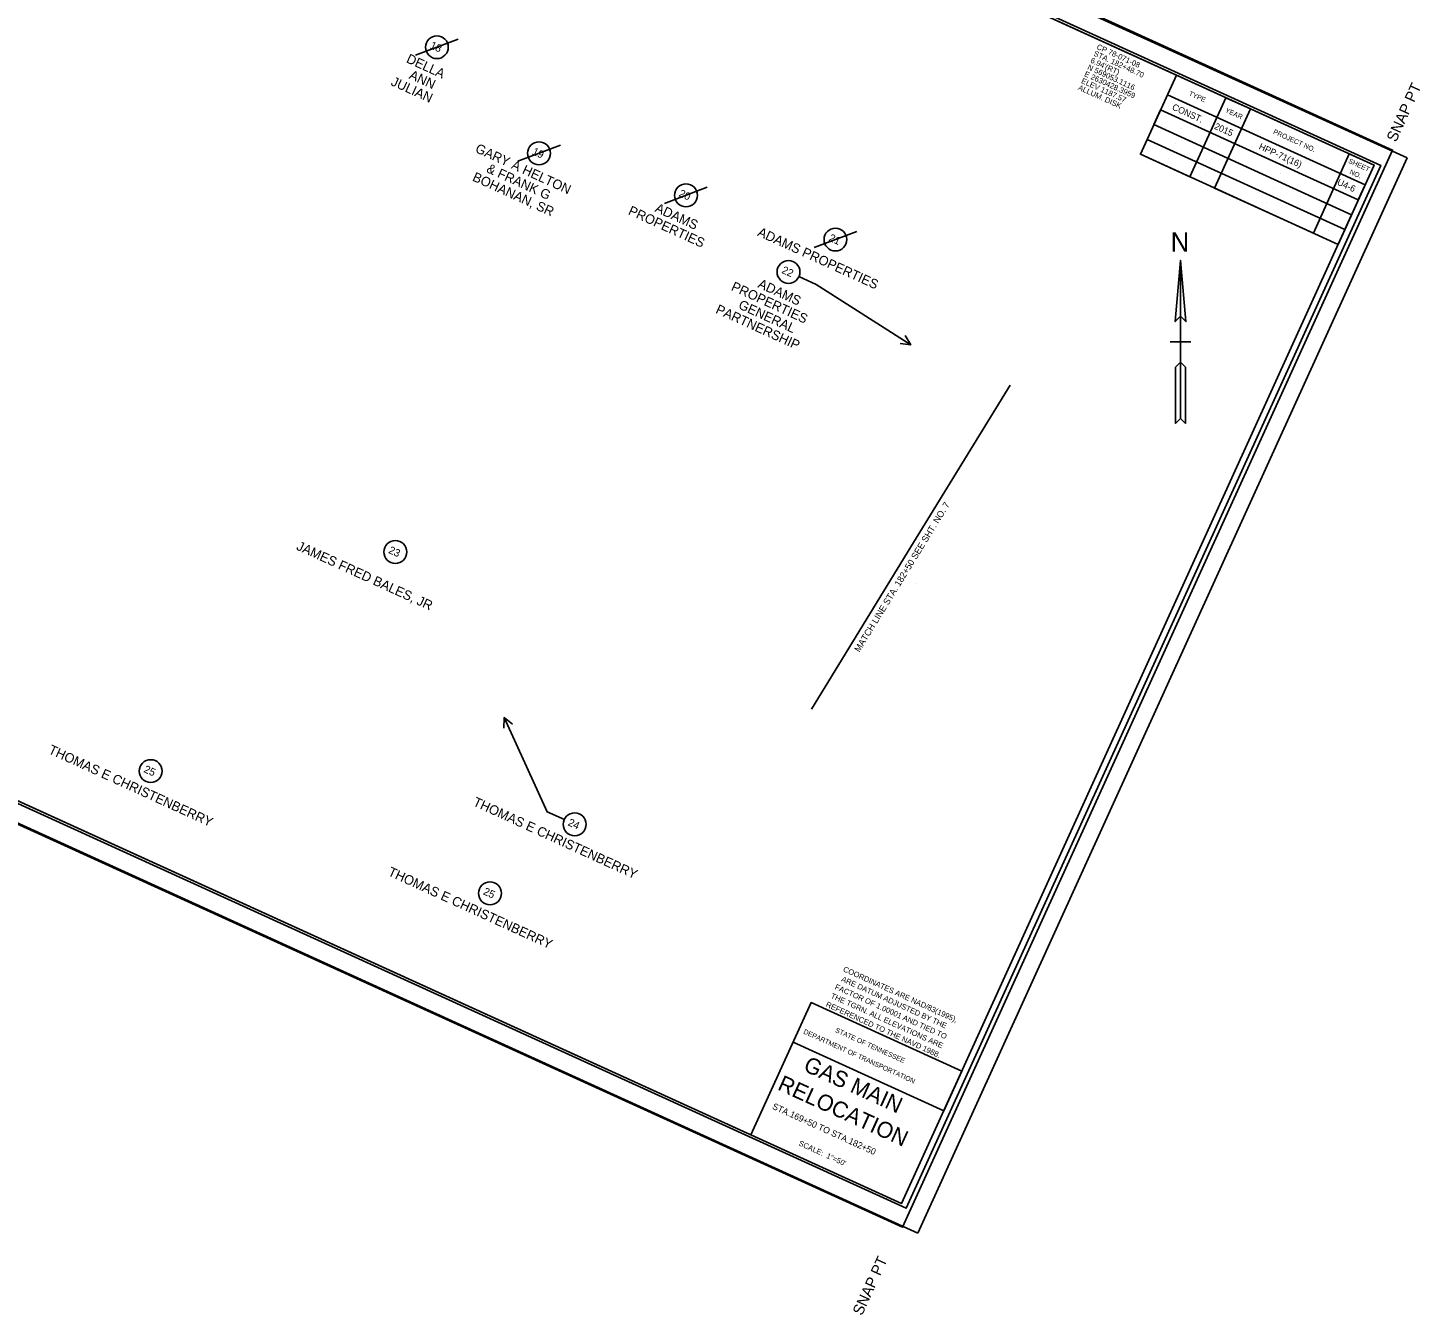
# Model space of a CAD drawing. Extents: x 2628810 to 2630911, y 568379 to 570218.
# Drawn here: x 2629628 to 2630911, y 568379 to 569564 of the extents above; entities that cross this region are included whole.
import ezdxf

# ---------------------------------------------------------------- set-up
doc = ezdxf.new("R2010")
doc.units = 0
for name, color, linetype in [('DESIGN - CENTERLINE - Proposed', 7, 'Continuous'), ('DESIGN - CENTERLINE - Proposed Text', 7, 'Continuous'), ('DESIGN - SCRATCH - User 1', 7, 'Continuous'), ('DESIGN - SHEET - Corner Text', 7, 'Continuous'), ('DESIGN - SHEET - Light Grid', 7, 'Continuous'), ('DESIGN - SHEET - Linework', 7, 'Continuous'), ('DESIGN - SHEET - Plot Shape', 7, 'Continuous'), ('SURVEY - PROPERTY - Owners', 7, 'Continuous'), ('SURVEY - PROPERTY - Tract Numbers', 7, 'Continuous')]:
    doc.layers.add(name, color=color, linetype=linetype)

msp = doc.modelspace()

# ---------------------------------------------------------------- linework, layer by layer
at = {"layer": 'DESIGN - CENTERLINE - Proposed Text'}
for p, q in [((2630689.9, 569274.6), (2630680.4, 569274.6)), ((2630699.3, 569274.6), (2630689.9, 569274.6))]:
    msp.add_line(p, q, dxfattribs=at)
for points in [[(2630689.9, 569349.6), (2630685, 569293.3), (2630689.9, 569298.2), (2630694.8, 569293.3), (2630689.9, 569349.6), (2630689.9, 569204.2), (2630694.4, 569199.6), (2630694.4, 569251.4), (2630689.9, 569255.9), (2630685.3, 569251.4), (2630685.3, 569199.6), (2630689.9, 569204.2)], [(2630349.9, 568936.6), (2630441.4, 569085.8), (2630532.9, 569234.9)]]:
    msp.add_lwpolyline(points, dxfattribs=at)
for points in [[(2630689.9, 569298.2), (2630694.8, 569293.3), (2630689.9, 569349.6)], [(2630685.3, 569199.6), (2630689.9, 569204.2), (2630689.9, 569255.9), (2630685.3, 569251.4)]]:
    msp.add_lwpolyline(points, close=True, dxfattribs=at)
at = {"layer": 'DESIGN - SCRATCH - User 1'}
for p, q in [((2630697.4, 569484.7), (2630697.4, 569484.7)), ((2630691.2, 569471.1), (2630691.2, 569471.1)), ((2630731.1, 569469.4), (2630731.1, 569469.4)), ((2630685, 569457.4), (2630685, 569457.4)), ((2630724.9, 569455.7), (2630724.9, 569455.7)), ((2630678.8, 569443.8), (2630678.8, 569443.8)), ((2630718.7, 569442.1), (2630718.7, 569442.1)), ((2630788, 569443.5), (2630788, 569443.5)), ((2630712.4, 569428.4), (2630712.4, 569428.4)), ((2630781.7, 569429.9), (2630781.7, 569429.9)), ((2630775.5, 569416.2), (2630775.5, 569416.2)), ((2630844.8, 569417.6), (2630844.8, 569417.6)), ((2630769.3, 569402.6), (2630769.3, 569402.6)), ((2630838.6, 569404), (2630838.6, 569404)), ((2630832.4, 569390.3), (2630832.4, 569390.3)), ((2630826.2, 569376.7), (2630826.2, 569376.7)), ((2630446.5, 569052.3), (2630446.5, 569052.3)), ((2630383, 568555.8), (2630383, 568555.8))]:
    msp.add_line(p, q, dxfattribs=at)
at = {"layer": 'DESIGN - SHEET - Light Grid'}
msp.add_lwpolyline([(2628921.9, 569166.8), (2630437.2, 568477), (2630874.3, 569437.1), (2629359, 570127)], close=True, dxfattribs=at)
at = {"layer": 'DESIGN - SHEET - Linework'}
for p, q in [((2629260.3, 570189.7), (2630898.6, 569443.9)), ((2630898.6, 569443.9), (2630448, 568454.2)), ((2628809.8, 569200), (2630448, 568454.2))]:
    msp.add_line(p, q, dxfattribs=at)
for points in [[(2629435.3, 570089.5), (2629000.3, 569133.8), (2630433, 568481.6), (2630868.1, 569437.3), (2629435.3, 570089.5)], [(2630686, 569520.1), (2630652.9, 569447.3), (2630834.9, 569364.4), (2630868.1, 569437.3), (2630845.3, 569447.6), (2630812.2, 569374.8), (2630721.2, 569416.2), (2630754.3, 569489), (2630731.6, 569499.4), (2630698.4, 569426.6), (2630652.9, 569447.3), (2630659.1, 569461), (2630841.1, 569378.1), (2630847.4, 569391.7), (2630665.3, 569474.6), (2630671.5, 569488.3), (2630853.6, 569405.4), (2630859.8, 569419.1), (2630677.8, 569501.9)], [(2630294.2, 568544.8), (2630349.6, 568666.4), (2630488.4, 568603.3), (2630471.8, 568566.9), (2630333, 568630)]]:
    msp.add_lwpolyline(points, dxfattribs=at)
at = {"layer": 'DESIGN - SHEET - Plot Shape'}
for points in [[(2629338, 570155.5), (2630885.2, 569451.1), (2630433.8, 568459.6), (2628886.6, 569164)], [(2629357.9, 570124.7), (2630868.1, 569437.3), (2630433, 568481.6), (2628922.9, 569169.1)]]:
    msp.add_lwpolyline(points, close=True, dxfattribs=at)
at = {"layer": 'SURVEY - PROPERTY - Tract Numbers'}
for p, q in [((2629985.3, 569538.5), (2630024.6, 569553.3)), ((2630079.4, 569440.9), (2630118.7, 569455.6)), ((2630214.7, 569402.1), (2630254, 569416.9)), ((2630352.3, 569361.4), (2630391.6, 569376.2))]:
    msp.add_line(p, q, dxfattribs=at)
for points in [[(2630354.3, 569327.4), (2630338.4, 569334.7)], [(2630441.4, 569272), (2630354.3, 569327.4)], [(2630436.4, 569280.4), (2630441.4, 569272), (2630431.7, 569273)], [(2630074.5, 568922.7), (2630066.9, 568928.8), (2630066.5, 568919.1)], [(2630066.9, 568928.8), (2630106.5, 568842.1), (2630122.4, 568834.9)]]:
    msp.add_lwpolyline(points, dxfattribs=at)
for centre in [(2630005, 569545.9), (2630099, 569448.2), (2630234.4, 569409.5), (2630372, 569368.8), (2630328.8, 569339), (2629966.7, 569081.2), (2629741.4, 568879.5), (2630131.9, 568830.5), (2630053.9, 568767)]:
    msp.add_circle(centre, 10.5, dxfattribs=at)

# ---------------------------------------------------------------- texts
at = {"layer": 'DESIGN - CENTERLINE - Proposed'}
for s, p in [('CP 78-071-08', (2630612.1, 569544.5)), ("6.94'(RT)", (2630606.4, 569532)), ('STA. 182+48.70', (2630609.3, 569538.3)), ('E 2630428.3959', (2630600.7, 569519.5)), ('N 569053.1116', (2630603.6, 569525.7)), ('ALLUM. DISK', (2630595, 569507)), ('ELEV 1187.57', (2630597.9, 569513.2))]:
    msp.add_text(s, height=5, rotation=335.5232, dxfattribs=at).set_placement(p)
at = {"layer": 'DESIGN - CENTERLINE - Proposed Text'}
msp.add_text('N', height=17.7, dxfattribs=at).set_placement((2630680.8, 569357.7))
msp.add_text('MATCH LINE STA. 182+50 SEE SHT. NO. 7', height=6, rotation=58.4832, dxfattribs=at).set_placement((2630394.1, 568988.5))
at = {"layer": 'DESIGN - SHEET - Corner Text'}
for s, height, rotation, p in [('  SNAP PT', 10, 65.5232, (2630885.2, 569451.1)), ('TYPE', 4.5, 335.5232, (2630697.1, 569501.7)), ('CONST.', 6, 335.5232, (2630681.5, 569488.7)), ('YEAR', 4.5, 335.5232, (2630730.5, 569486.3)), ('2015', 6, 335.5232, (2630720.4, 569471)), ('PROJECT NO.', 4.5, 335.5232, (2630774.8, 569466.5)), ('HPP-71(16)', 6, 335.5232, (2630761.4, 569452.3)), ('SHEET', 4.5, 335.5232, (2630844, 569439.6)), ('NO.', 4.5, 335.5232, (2630845.1, 569429.5)), ('U4-6', 6, 335.5232, (2630833.5, 569419.5)), ('ARE DATUM ADJUSTED BY THE', 5, 335.5232, (2630376.9, 568686.3)), ('COORDINATES ARE NAD/83(1995),', 5, 335.5232, (2630378.6, 568695.4)), ('THE TGRN. ALL ELEVATIONS ARE', 5, 335.5232, (2630367.2, 568670.9)), ('FACTOR OF 1.00001 AND TIED TO', 5, 335.5232, (2630371, 568679.1)), ('REFERENCED TO THE NAVD 1988.', 5, 335.5232, (2630362.7, 568663)), ('DEPARTMENT OF TRANSPORTATION', 4.5, 335.5232, (2630342.1, 568638.1)), ('STATE OF TENNESSEE', 4.5, 335.5232, (2630371.4, 568639.4)), ('GAS MAIN ', 14.76, 335.5232, (2630341.6, 568604.1)), ('RELOCATION', 14.76, 335.5232, (2630317.8, 568586.6)), ('STA.169+50 TO STA.182+50', 5.906, 335.5232, (2630313.3, 568568.8)), ('SCALE:  1"=50\'', 4.922, 335.5232, (2630337.7, 568535.2)), ('SNAP PT  ', 10, 65.5232, (2630396.5, 568377.7))]:
    msp.add_text(s, height=height, rotation=rotation, dxfattribs=at).set_placement(p)
at = {"layer": 'SURVEY - PROPERTY - Owners'}
for s, p in [('DELLA', (2629976.1, 569532.2)), ('ANN', (2629978.7, 569517.3)), ('JULIAN', (2629961.9, 569511.2)), ('GARY A HELTON', (2630039.6, 569449.6)), ('& FRANK G', (2630049.9, 569431.2)), ('BOHANAN, SR', (2630037, 569423.3)), ('PROPERTIES', (2630180.5, 569392.3)), ('ADAMS', (2630205.1, 569394.8)), ('ADAMS PROPERTIES', (2630299.6, 569372.6)), ('PROPERTIES', (2630275.3, 569322.5)), ('ADAMS', (2630299.9, 569325)), ('PARTNERSHIP', (2630261, 569301.5)), ('GENERAL', (2630281.9, 569305.7)), ('JAMES FRED BALES, JR', (2629874.9, 569083.6)), ('THOMAS E CHRISTENBERRY', (2629646.5, 568896.1)), ('THOMAS E CHRISTENBERRY', (2630037.5, 568848)), ('THOMAS E CHRISTENBERRY', (2629959.2, 568783.7))]:
    msp.add_text(s, height=8.75, rotation=335.5232, dxfattribs=at).set_placement(p)
at = {"layer": 'SURVEY - PROPERTY - Tract Numbers'}
for s, p in [('18', (2629998, 569545.2)), ('19', (2630092.1, 569447.5)), ('20', (2630227.2, 569408.9)), ('21', (2630365.3, 569368)), ('22', (2630321.9, 569338.3)), ('23', (2629959.8, 569080.5)), ('25', (2629734.4, 568878.8)), ('24', (2630125, 568829.8)), ('25', (2630047, 568766.3))]:
    msp.add_text(s, height=7, rotation=335.5232, dxfattribs=at).set_placement(p)

doc.saveas('drawing.dxf')
